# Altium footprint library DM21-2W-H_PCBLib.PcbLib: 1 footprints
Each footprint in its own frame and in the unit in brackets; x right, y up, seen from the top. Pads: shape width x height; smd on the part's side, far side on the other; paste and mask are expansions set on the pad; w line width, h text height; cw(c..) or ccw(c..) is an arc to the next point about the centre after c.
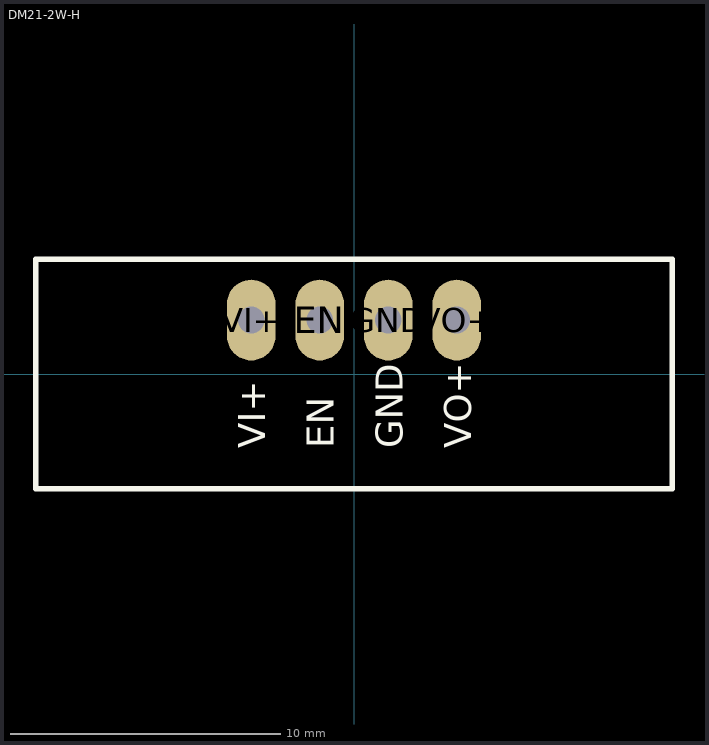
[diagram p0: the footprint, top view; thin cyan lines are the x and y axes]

## DM21-2W-H [mm]
pads (4):
  oval 1.8x3 hole 1: EN(-1.27,2) GND(1.27,2) VI+(-3.81,2) VO+(3.81,2)
TopOverlay:
  lines w0.2: -11.8,-4.25 11.8,-4.25 11.8,4.25 -11.8,4.25 -11.8,-4.25
  text "VI+" at -3.3,-2.75 h1
  text "EN" at -0.75,-2.75 h1
  text "GND" at 1.8,-2.75 h1
  text "VO+" at 4.35,-2.75 h1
